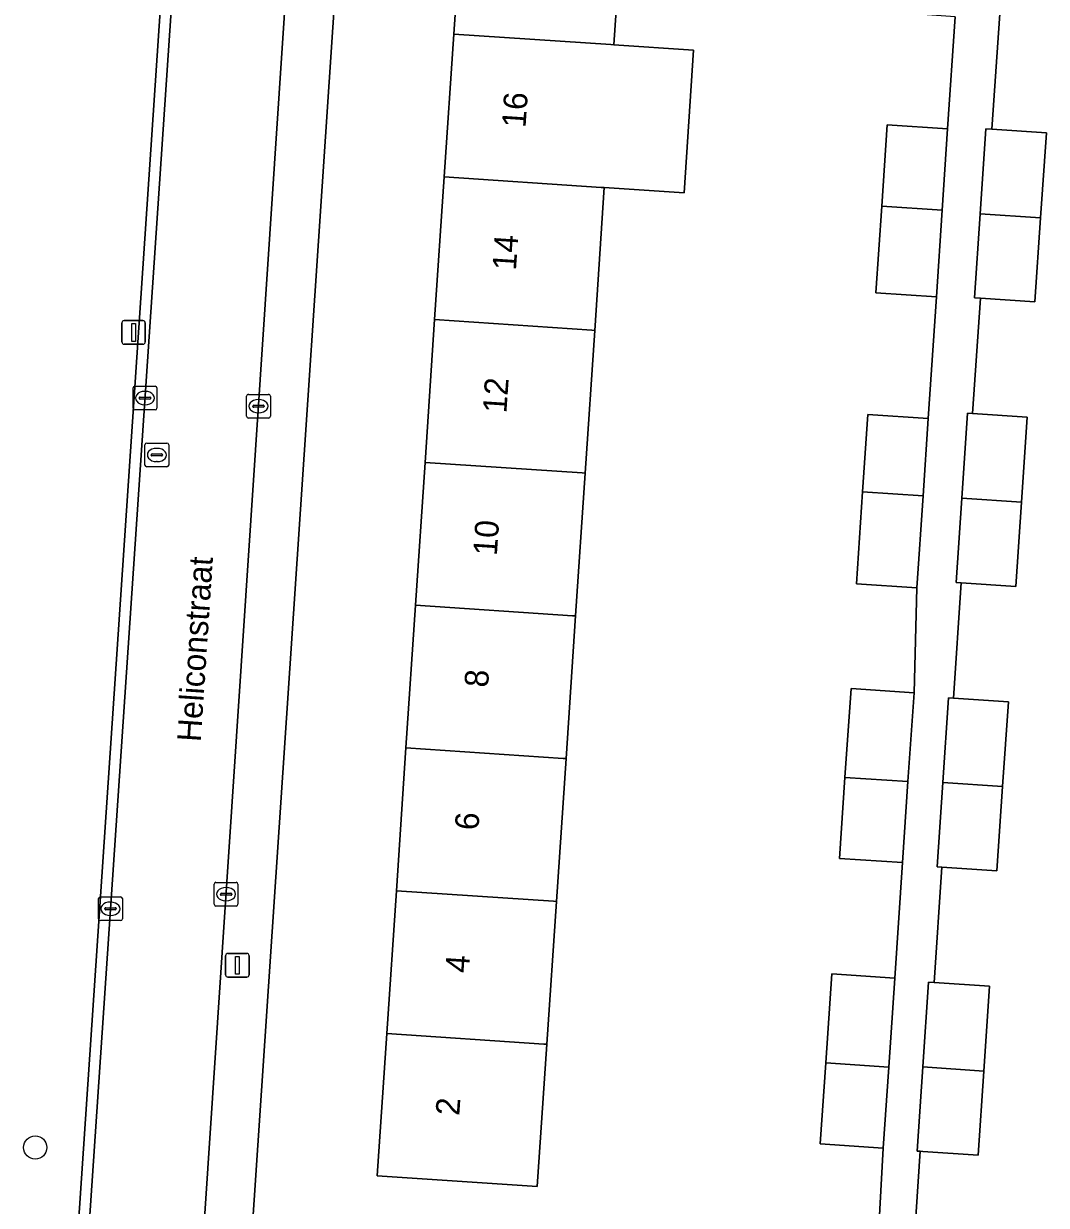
# Model space of a CAD drawing. Extents: x 161848 to 162726, y 385382 to 386521.
# Drawn here: x 161958.47 to 162001.57, y 386025.38 to 386075.17 of the extents above; entities that cross this region are included whole.
import ezdxf

# ---------------------------------------------------------------- set-up
doc = ezdxf.new("R2010")
doc.units = 0
for name, color, linetype in [('IMGEO_Boom', 7, 'Continuous'), ('IMGEO_Erf', 7, 'Continuous'), ('IMGEO_Groenvoorziening', 7, 'Continuous'), ('IMGEO_Kolk', 7, 'Continuous'), ('IMGEO_Lichtmast', 7, 'Continuous'), ('IMGEO_Openbare_ruimte_label', 7, 'Continuous'), ('IMGEO_Pand', 7, 'Continuous'), ('IMGEO_Pand_nummerreeks', 7, 'Continuous'), ('IMGEO_Rijbaan_lokaal_open', 7, 'Continuous'), ('IMGEO_Rioolput', 7, 'Continuous'), ('IMGEO_Verkeerseiland_open', 7, 'Continuous'), ('IMGEO_Voetpad_open', 7, 'Continuous')]:
    doc.layers.add(name, color=color, linetype=linetype)

msp = doc.modelspace()

# ---------------------------------------------------------------- linework, layer by layer
at = {"layer": 'IMGEO_Boom'}
msp.add_circle((161958.961, 386027.82), 0.489, dxfattribs=at)
at = {"layer": 'IMGEO_Erf'}
for points in [[(161996.938, 386063.657), (161994.389, 386063.828), (161994.634, 386067.482), (161994.864, 386070.913), (161997.413, 386070.742), (161997.73, 386075.466), (161995.181, 386075.637), (161995.441, 386079.514), (161995.659, 386082.77), (161998.208, 386082.599), (161998.537, 386087.498), (161995.988, 386087.669), (161996.248, 386091.546), (161996.466, 386094.802), (161999.015, 386094.631), (161999.397, 386100.351), (161977.152, 386101.835), (161975.481, 386101.597)], [(161973.071, 386098.474), (161968.121, 386024.56)], [(161983.749, 386080.299), (161983.346, 386074.283), (161986.707, 386074.057), (161986.303, 386068.041), (161982.942, 386068.267), (161982.539, 386062.251), (161982.136, 386056.236), (161981.732, 386050.22), (161981.329, 386044.204), (161980.925, 386038.188), (161980.522, 386032.172), (161980.12, 386026.181), (161973.375, 386026.633), (161973.777, 386032.624), (161974.18, 386038.64), (161974.584, 386044.656), (161974.987, 386050.672), (161975.391, 386056.688), (161975.794, 386062.703), (161976.197, 386068.719), (161976.601, 386074.735), (161977.004, 386080.751)], [(161999.605, 386075.583), (161999.276, 386070.725), (162001.573, 386070.571), (162001.332, 386066.994), (162001.093, 386063.447), (161998.795, 386063.601), (161998.466, 386058.742), (162000.765, 386058.587), (162000.524, 386055.011), (162000.285, 386051.464), (161997.985, 386051.618), (161997.655, 386046.76), (161999.972, 386046.604), (161999.73, 386043.027), (161999.49, 386039.48), (161997.174, 386039.636), (161996.845, 386034.777), (161999.178, 386034.62), (161998.936, 386031.043), (161998.696, 386027.496), (161996.364, 386027.653), (161996.248, 386027.661), (161995.913, 386022.549)], [(161994.411, 386022.651), (161994.699, 386027.79), (161992.043, 386027.972), (161992.277, 386031.383), (161992.534, 386035.132), (161995.19, 386034.95), (161995.506, 386039.822), (161992.85, 386040.004), (161993.084, 386043.415), (161993.341, 386047.164), (161995.997, 386046.982), (161996.117, 386051.403), (161993.568, 386051.574), (161993.828, 386055.451), (161994.046, 386058.707), (161996.595, 386058.536), (161996.938, 386063.657)]]:
    msp.add_lwpolyline(points, dxfattribs=at)
at = {"layer": 'IMGEO_Groenvoorziening'}
msp.add_lwpolyline([(161961.227, 386024.551), (161960.785, 386024.65), (161965.608, 386096.137), (161966.064, 386096.102)], dxfattribs=at)
at = {"layer": 'IMGEO_Kolk'}
for p, q in [((161963.161, 386059.899), (161964.013, 386059.899)), ((161963.086, 386058.973), (161963.086, 386059.825)), ((161963.345, 386059.393), (161963.345, 386059.405)), ((161963.388, 386059.442), (161963.786, 386059.442)), ((161963.574, 386059.679), (161963.599, 386059.679)), ((161963.829, 386059.405), (161963.829, 386059.393)), ((161964.087, 386059.825), (161964.087, 386058.973)), ((161967.869, 386058.629), (161967.869, 386059.481)), ((161967.944, 386059.555), (161968.796, 386059.555)), ((161968.87, 386059.481), (161968.87, 386058.629)), ((161964.013, 386058.899), (161963.161, 386058.899)), ((161963.783, 386059.356), (161963.385, 386059.356)), ((161963.597, 386059.119), (161963.572, 386059.119)), ((161968.128, 386059.049), (161968.128, 386059.061)), ((161968.566, 386059.012), (161968.168, 386059.012)), ((161968.171, 386059.098), (161968.569, 386059.098)), ((161968.357, 386059.335), (161968.382, 386059.335)), ((161968.612, 386059.061), (161968.612, 386059.049)), ((161968.796, 386058.555), (161967.944, 386058.555)), ((161968.38, 386058.775), (161968.355, 386058.775)), ((161966.578, 386038.993), (161967.43, 386038.993)), ((161966.503, 386038.067), (161966.503, 386038.919)), ((161966.762, 386038.487), (161966.762, 386038.499)), ((161966.805, 386038.536), (161967.203, 386038.536)), ((161966.991, 386038.773), (161967.016, 386038.773)), ((161967.246, 386038.499), (161967.246, 386038.487)), ((161967.504, 386038.919), (161967.504, 386038.067)), ((161961.632, 386037.455), (161961.632, 386038.307)), ((161961.707, 386038.381), (161962.559, 386038.381)), ((161962.12, 386038.161), (161962.145, 386038.161)), ((161962.633, 386038.307), (161962.633, 386037.455)), ((161967.43, 386037.993), (161966.578, 386037.993)), ((161967.2, 386038.45), (161966.802, 386038.45)), ((161967.014, 386038.213), (161966.989, 386038.213)), ((161961.891, 386037.875), (161961.891, 386037.887)), ((161962.329, 386037.838), (161961.931, 386037.838)), ((161961.934, 386037.924), (161962.332, 386037.924)), ((161962.143, 386037.601), (161962.118, 386037.601)), ((161962.375, 386037.887), (161962.375, 386037.875)), ((161962.559, 386037.381), (161961.707, 386037.381))]:
    msp.add_line(p, q, dxfattribs=at)
for points in [[(161963.161, 386059.899), (161964.013, 386059.899)], [(161963.086, 386058.973), (161963.086, 386059.825)], [(161964.087, 386059.825), (161964.087, 386058.973)], [(161967.869, 386058.629), (161967.869, 386059.481)], [(161967.944, 386059.555), (161968.796, 386059.555)], [(161968.87, 386059.481), (161968.87, 386058.629)], [(161964.013, 386058.899), (161963.161, 386058.899)], [(161968.796, 386058.555), (161967.944, 386058.555)], [(161966.578, 386038.993), (161967.43, 386038.993)], [(161966.503, 386038.067), (161966.503, 386038.919)], [(161967.504, 386038.919), (161967.504, 386038.067)], [(161961.632, 386037.455), (161961.632, 386038.307)], [(161961.707, 386038.381), (161962.559, 386038.381)], [(161962.633, 386038.307), (161962.633, 386037.455)], [(161967.43, 386037.993), (161966.578, 386037.993)], [(161962.559, 386037.381), (161961.707, 386037.381)]]:
    msp.add_lwpolyline(points, dxfattribs=at)
for centre, radius, start, end in [((161963.163, 386059.823), 0.0765, 91.552, 178.448), ((161963.163, 386059.823), 0.0765, 91.552, 178.448), ((161964.011, 386059.823), 0.0765, 1.552, 88.448), ((161964.011, 386059.823), 0.0765, 1.552, 88.448), ((161963.385, 386059.402), 0.0403, 85.8775, 175.7526), ((161963.382, 386059.392), 0.0366, 178.938, 274.7102), ((161963.786, 386059.399), 0.043, 264.8664, 352.4533), ((161963.79, 386059.404), 0.0386, 1.7309, 96.639), ((161967.946, 386059.479), 0.0765, 91.552, 178.448), ((161967.946, 386059.479), 0.0765, 91.552, 178.448), ((161968.794, 386059.479), 0.0765, 1.552, 88.448), ((161968.794, 386059.479), 0.0765, 1.552, 88.448), ((161963.163, 386058.975), 0.0765, 181.552, 268.448), ((161963.163, 386058.975), 0.0765, 181.552, 268.448), ((161964.011, 386058.975), 0.0765, 271.552, 358.448), ((161964.011, 386058.975), 0.0765, 271.552, 358.448), ((161968.168, 386059.058), 0.0403, 85.8775, 175.7526), ((161968.165, 386059.048), 0.0366, 178.938, 274.7102), ((161968.569, 386059.055), 0.043, 264.8664, 352.4533), ((161968.573, 386059.06), 0.0386, 1.7309, 96.639), ((161967.946, 386058.631), 0.0765, 181.552, 268.448), ((161967.946, 386058.631), 0.0765, 181.552, 268.448), ((161968.794, 386058.631), 0.0765, 271.552, 358.448), ((161968.794, 386058.631), 0.0765, 271.552, 358.448), ((161966.58, 386038.917), 0.0765, 91.552, 178.448), ((161966.58, 386038.917), 0.0765, 91.552, 178.448), ((161967.428, 386038.917), 0.0765, 1.552, 88.448), ((161967.428, 386038.917), 0.0765, 1.552, 88.448), ((161966.802, 386038.496), 0.0403, 85.8775, 175.7526), ((161966.799, 386038.486), 0.0366, 178.938, 274.7102), ((161967.203, 386038.493), 0.043, 264.8664, 352.4533), ((161967.207, 386038.498), 0.0386, 1.7309, 96.639), ((161961.709, 386038.305), 0.0765, 91.552, 178.448), ((161961.709, 386038.305), 0.0765, 91.552, 178.448), ((161962.557, 386038.305), 0.0765, 1.552, 88.448), ((161962.557, 386038.305), 0.0765, 1.552, 88.448), ((161966.58, 386038.069), 0.0765, 181.552, 268.448), ((161966.58, 386038.069), 0.0765, 181.552, 268.448), ((161967.428, 386038.069), 0.0765, 271.552, 358.448), ((161967.428, 386038.069), 0.0765, 271.552, 358.448), ((161961.931, 386037.884), 0.0403, 85.8775, 175.7526), ((161961.928, 386037.874), 0.0366, 178.938, 274.7102), ((161962.332, 386037.881), 0.043, 264.8664, 352.4533), ((161962.336, 386037.886), 0.0386, 1.7309, 96.639), ((161961.709, 386037.457), 0.0765, 181.552, 268.448), ((161961.709, 386037.457), 0.0765, 181.552, 268.448), ((161962.557, 386037.457), 0.0765, 271.552, 358.448), ((161962.557, 386037.457), 0.0765, 271.552, 358.448)]:
    msp.add_arc(centre, radius, start, end, dxfattribs=at)
for centre, major_axis, ratio, start_param, end_param in [((161963.573, 386059.399), (-0.387, 0.002), 0.722429, 4.712389, 7.853982), ((161963.598, 386059.399), (-0.39, 0.002), 0.717154, 1.570796, 4.712389), ((161968.356, 386059.055), (-0.387, 0.002), 0.722429, 4.712389, 7.853982), ((161968.381, 386059.055), (-0.39, 0.002), 0.717154, 1.570796, 4.712389), ((161966.99, 386038.493), (-0.387, 0.002), 0.722429, 4.712389, 7.853982), ((161967.015, 386038.493), (-0.39, 0.002), 0.717154, 1.570796, 4.712389), ((161962.119, 386037.881), (-0.387, 0.002), 0.722429, 4.712389, 7.853982), ((161962.144, 386037.881), (-0.39, 0.002), 0.717154, 1.570796, 4.712389)]:
    msp.add_ellipse(centre, major_axis=major_axis, ratio=ratio, start_param=start_param, end_param=end_param, dxfattribs=at)
at = {"layer": 'IMGEO_Lichtmast'}
for p, q in [((161962.61, 386061.763), (161962.61, 386062.563)), ((161962.61, 386062.563), (161962.61, 386061.763)), ((161962.71, 386062.663), (161963.5, 386062.663)), ((161963.5, 386062.663), (161962.71, 386062.663)), ((161963.6, 386062.563), (161963.6, 386061.763)), ((161963.6, 386061.763), (161963.6, 386062.563)), ((161963.5, 386061.663), (161962.71, 386061.663)), ((161962.71, 386061.663), (161963.5, 386061.663)), ((161967.083, 386035.997), (161967.873, 386035.997)), ((161967.873, 386035.997), (161967.083, 386035.997)), ((161966.983, 386035.097), (161966.983, 386035.897)), ((161966.983, 386035.897), (161966.983, 386035.097)), ((161967.973, 386035.897), (161967.973, 386035.097)), ((161967.973, 386035.097), (161967.973, 386035.897)), ((161967.873, 386034.997), (161967.083, 386034.997)), ((161967.083, 386034.997), (161967.873, 386034.997))]:
    msp.add_line(p, q, dxfattribs=at)
for points in [[(161963.03, 386062.538), (161963.18, 386062.538), (161963.18, 386061.788), (161963.03, 386061.788), (161963.03, 386062.538)], [(161967.403, 386035.872), (161967.553, 386035.872), (161967.553, 386035.122), (161967.403, 386035.122), (161967.403, 386035.872)]]:
    msp.add_lwpolyline(points, dxfattribs=at)
for centre, start, end in [((161962.71, 386062.563), 90, 180), ((161962.71, 386062.563), 90, 180), ((161963.5, 386062.563), 0, 90), ((161963.5, 386062.563), 360, 90), ((161962.71, 386061.763), 180, 270), ((161962.71, 386061.763), 180, 270), ((161963.5, 386061.763), 270, 0), ((161963.5, 386061.763), 270, 0), ((161967.083, 386035.897), 90, 180), ((161967.083, 386035.897), 90, 180), ((161967.873, 386035.897), 0, 90), ((161967.873, 386035.897), 360, 90), ((161967.083, 386035.097), 180, 270), ((161967.083, 386035.097), 180, 270), ((161967.873, 386035.097), 270, 0), ((161967.873, 386035.097), 270, 0)]:
    msp.add_arc(centre, 0.1, start, end, dxfattribs=at)
at = {"layer": 'IMGEO_Pand'}
for points in [[(161983.749, 386080.299), (161983.624, 386080.307), (161977.004, 386080.751), (161976.601, 386074.735), (161983.221, 386074.291), (161983.346, 386074.283)], [(161983.346, 386074.283), (161983.221, 386074.291), (161976.601, 386074.735), (161976.197, 386068.719), (161982.817, 386068.275), (161982.942, 386068.267), (161986.303, 386068.041), (161986.707, 386074.057)], [(161997.413, 386070.742), (161994.864, 386070.913), (161994.634, 386067.482), (161997.183, 386067.311)], [(161999.276, 386070.725), (161999.021, 386070.742), (161998.78, 386067.167), (162001.332, 386066.994), (162001.573, 386070.571)], [(161982.942, 386068.267), (161982.817, 386068.275), (161976.197, 386068.719), (161975.794, 386062.703), (161982.413, 386062.259), (161982.539, 386062.251)], [(161997.183, 386067.311), (161994.634, 386067.482), (161994.389, 386063.828), (161996.938, 386063.657)], [(162001.332, 386066.994), (161998.78, 386067.167), (161998.54, 386063.618), (161998.795, 386063.601), (162001.093, 386063.447)], [(161982.539, 386062.251), (161982.413, 386062.259), (161975.794, 386062.703), (161975.391, 386056.688), (161982.01, 386056.244), (161982.136, 386056.236)], [(161996.595, 386058.536), (161994.046, 386058.707), (161993.828, 386055.451), (161996.377, 386055.28)], [(161998.466, 386058.742), (161998.247, 386058.757), (161998.006, 386055.182), (162000.524, 386055.011), (162000.765, 386058.587)], [(161982.136, 386056.236), (161982.01, 386056.244), (161975.391, 386056.688), (161974.987, 386050.672), (161981.607, 386050.228), (161981.732, 386050.22)], [(161993.568, 386051.574), (161996.117, 386051.403), (161996.377, 386055.28), (161993.828, 386055.451)], [(162000.524, 386055.011), (161998.006, 386055.182), (161997.767, 386051.633), (161997.985, 386051.618), (162000.285, 386051.464)], [(161981.732, 386050.22), (161981.607, 386050.228), (161974.987, 386050.672), (161974.584, 386044.656), (161981.203, 386044.212), (161981.329, 386044.204)], [(161995.997, 386046.982), (161993.341, 386047.164), (161993.084, 386043.415), (161995.74, 386043.237)], [(161997.655, 386046.76), (161997.448, 386046.774), (161997.207, 386043.199), (161999.73, 386043.027), (161999.972, 386046.604)], [(161981.329, 386044.204), (161981.203, 386044.212), (161974.584, 386044.656), (161974.18, 386038.64), (161980.8, 386038.196), (161980.925, 386038.188)], [(161992.85, 386040.004), (161995.506, 386039.822), (161995.74, 386043.237), (161993.084, 386043.415)], [(161999.73, 386043.027), (161997.207, 386043.199), (161996.967, 386039.65), (161997.174, 386039.636), (161999.49, 386039.48)], [(161980.925, 386038.188), (161980.8, 386038.196), (161974.18, 386038.64), (161973.777, 386032.624), (161980.397, 386032.18), (161980.522, 386032.172)], [(161995.19, 386034.95), (161992.534, 386035.132), (161992.277, 386031.383), (161994.933, 386031.205)], [(161996.845, 386034.777), (161996.603, 386034.793), (161996.362, 386031.218), (161998.936, 386031.043), (161999.178, 386034.62)], [(161980.522, 386032.172), (161980.397, 386032.18), (161973.777, 386032.624), (161973.375, 386026.633), (161980.12, 386026.181)], [(161992.043, 386027.972), (161994.699, 386027.79), (161994.933, 386031.205), (161992.277, 386031.383)], [(161998.936, 386031.043), (161996.362, 386031.218), (161996.124, 386027.669), (161996.248, 386027.661), (161996.364, 386027.653), (161998.696, 386027.496)]]:
    msp.add_lwpolyline(points, close=True, dxfattribs=at)
at = {"layer": 'IMGEO_Rijbaan_lokaal_open'}
for points in [[(161970.952, 386098.074), (161966.224, 386098.31), (161966.064, 386096.102), (161961.227, 386024.551), (161960.651, 386015.914), (161965.521, 386015.701)], [(161965.532, 386016.361), (161970.952, 386098.074)]]:
    msp.add_lwpolyline(points, dxfattribs=at)
at = {"layer": 'IMGEO_Rioolput'}
for p, q in [((161963.585, 386056.574), (161963.585, 386057.426)), ((161963.66, 386057.5), (161964.512, 386057.5)), ((161964.586, 386057.426), (161964.586, 386056.574)), ((161963.844, 386056.994), (161963.844, 386057.006)), ((161964.282, 386056.957), (161963.884, 386056.957)), ((161963.887, 386057.043), (161964.285, 386057.043)), ((161964.073, 386057.28), (161964.098, 386057.28)), ((161964.328, 386057.006), (161964.328, 386056.994)), ((161964.512, 386056.5), (161963.66, 386056.5)), ((161964.096, 386056.72), (161964.071, 386056.72))]:
    msp.add_line(p, q, dxfattribs=at)
for points in [[(161963.585, 386056.574), (161963.585, 386057.426)], [(161963.66, 386057.5), (161964.512, 386057.5)], [(161964.586, 386057.426), (161964.586, 386056.574)], [(161964.512, 386056.5), (161963.66, 386056.5)]]:
    msp.add_lwpolyline(points, dxfattribs=at)
for centre, radius, start, end in [((161963.662, 386057.424), 0.0765, 91.552, 178.448), ((161963.662, 386057.424), 0.0765, 91.552, 178.448), ((161964.51, 386057.424), 0.0765, 1.552, 88.448), ((161964.51, 386057.424), 0.0765, 1.552, 88.448), ((161963.884, 386057.003), 0.0403, 85.8775, 175.7526), ((161963.881, 386056.993), 0.0366, 178.938, 274.7102), ((161964.285, 386057), 0.043, 264.8664, 352.4533), ((161964.289, 386057.005), 0.0386, 1.7309, 96.639), ((161963.662, 386056.576), 0.0765, 181.552, 268.448), ((161963.662, 386056.576), 0.0765, 181.552, 268.448), ((161964.51, 386056.576), 0.0765, 271.552, 358.448), ((161964.51, 386056.576), 0.0765, 271.552, 358.448)]:
    msp.add_arc(centre, radius, start, end, dxfattribs=at)
for centre, major_axis, ratio, start_param, end_param in [((161964.072, 386057), (-0.387, 0.002), 0.722429, 4.712389, 7.853982), ((161964.097, 386057), (-0.39, 0.002), 0.717154, 1.570796, 4.712389)]:
    msp.add_ellipse(centre, major_axis=major_axis, ratio=ratio, start_param=start_param, end_param=end_param, dxfattribs=at)
at = {"layer": 'IMGEO_Verkeerseiland_open'}
msp.add_lwpolyline([(161965.608, 386096.137), (161960.785, 386024.65), (161961.227, 386024.551), (161966.064, 386096.102)], close=True, dxfattribs=at)
at = {"layer": 'IMGEO_Voetpad_open'}
for points in [[(161967.557, 386016.132), (161968.081, 386023.961), (161968.121, 386024.56), (161973.071, 386098.474), (161973.273, 386099.425)], [(161970.952, 386098.074), (161965.532, 386016.361)], [(161997.73, 386075.466), (161997.413, 386070.742), (161997.183, 386067.311), (161996.938, 386063.657), (161996.595, 386058.536), (161996.377, 386055.28), (161996.117, 386051.403), (161995.997, 386046.982), (161995.74, 386043.237), (161995.506, 386039.822), (161995.19, 386034.95), (161994.933, 386031.205), (161994.699, 386027.79), (161994.411, 386022.651)], [(161995.913, 386022.549), (161996.248, 386027.661), (161996.124, 386027.669), (161996.362, 386031.218), (161996.603, 386034.793), (161996.845, 386034.777), (161997.174, 386039.636), (161996.967, 386039.65), (161997.207, 386043.199), (161997.448, 386046.774), (161997.655, 386046.76), (161997.985, 386051.618), (161997.767, 386051.633), (161998.006, 386055.182), (161998.247, 386058.757), (161998.466, 386058.742), (161998.795, 386063.601), (161998.54, 386063.618), (161998.78, 386067.167), (161999.021, 386070.742), (161999.276, 386070.725), (161999.605, 386075.583)]]:
    msp.add_lwpolyline(points, dxfattribs=at)

# ---------------------------------------------------------------- texts
at = {"layer": 'IMGEO_Openbare_ruimte_label'}
msp.add_text('Heliconstraat', height=1, rotation=86.2164, dxfattribs=at).set_placement((161965.935, 386044.891))
at = {"layer": 'IMGEO_Pand_nummerreeks'}
for s, rotation, p in [('16', 86.1614, (161979.622, 386070.769)), ('14', 86.1634, (161979.219, 386064.757)), ('12', 86.1634, (161978.816, 386058.742)), ('10', 86.1634, (161978.413, 386052.737)), ('8', 86.1634, (161978.041, 386047.185)), ('6', 86.1634, (161977.637, 386041.169)), ('4', 86.1634, (161977.234, 386035.157)), ('2', 86.1634, (161976.83, 386029.143))]:
    msp.add_text(s, height=1, rotation=rotation, dxfattribs=at).set_placement(p)

doc.saveas('drawing.dxf')
